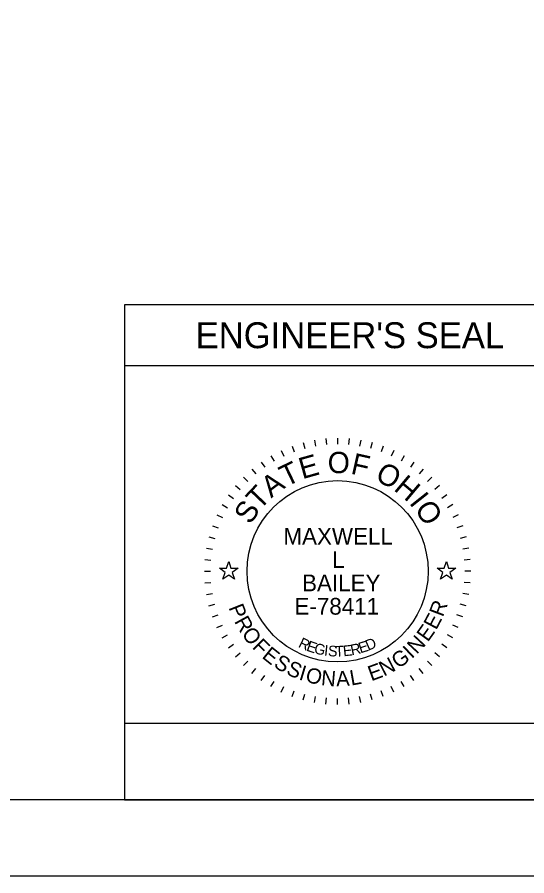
# Model space of a CAD drawing. Extents: x 0 to 34, y 0 to 22.
# Drawn here: x 6.64 to 9.99, y 0 to 5.64 of the extents above; entities that cross this region are included whole.
import ezdxf

# ---------------------------------------------------------------- set-up
doc = ezdxf.new("R2010")
doc.units = 0
for name, color, linetype in [('SH_Border', 7, 'Continuous'), ('SH_Cut_Line', 7, 'Continuous'), ('SH_Data', 7, 'Continuous'), ('SH_Seal', 7, 'Continuous')]:
    doc.layers.add(name, color=color, linetype=linetype)

msp = doc.modelspace()

# ---------------------------------------------------------------- linework, layer by layer
at = {"layer": 'SH_Border'}
msp.add_lwpolyline([(1.5, 21.5), (33.5, 21.5), (33.5, 0.5), (1.5, 0.5)], close=True, dxfattribs=at)
at = {"layer": 'SH_Cut_Line'}
msp.add_lwpolyline([(0, 0), (34, 0), (34, 22), (0, 22)], close=True, dxfattribs=at)
at = {"layer": 'SH_Data'}
for p, q in [((10.15, 3.75), (7.35, 3.75)), ((7.35, 3.75), (7.35, 0.5)), ((10.15, 3.35), (7.35, 3.35)), ((10.15, 0.5), (7.35, 0.5))]:
    msp.add_line(p, q, dxfattribs=at)
msp.add_lwpolyline([(10.15, 0.5), (10.15, 1), (7.35, 1), (7.35, 0.5)], close=True, dxfattribs=at)
at = {"layer": 'SH_Seal'}
for p, q in [((8.4507, 2.8222), (8.4644, 2.7846)), ((8.5235, 2.8452), (8.5339, 2.8065)), ((8.5981, 2.8617), (8.605, 2.8223)), ((8.6737, 2.8717), (8.6772, 2.8318)), ((8.75, 2.875), (8.75, 2.835)), ((8.8263, 2.8717), (8.8228, 2.8318)), ((8.9019, 2.8617), (8.895, 2.8223)), ((8.9765, 2.8452), (8.9661, 2.8065)), ((9.0493, 2.8222), (9.0356, 2.7846)), ((8.3802, 2.793), (8.3971, 2.7568)), ((9.1198, 2.793), (9.1029, 2.7568)), ((8.2481, 2.7168), (8.2711, 2.684)), ((8.3125, 2.7578), (8.3325, 2.7231)), ((9.1875, 2.7578), (9.1675, 2.7231)), ((9.2519, 2.7168), (9.2289, 2.684)), ((8.1876, 2.6703), (8.2133, 2.6396)), ((9.3124, 2.6703), (9.2867, 2.6396)), ((8.1313, 2.6187), (8.1596, 2.5904)), ((9.3687, 2.6187), (9.3404, 2.5904)), ((8.0797, 2.5624), (8.1104, 2.5367)), ((9.4203, 2.5624), (9.3896, 2.5367)), ((8.0332, 2.5019), (8.066, 2.4789)), ((9.4668, 2.5019), (9.434, 2.4789)), ((7.9922, 2.4375), (8.0269, 2.4175)), ((9.5078, 2.4375), (9.4731, 2.4175)), ((7.957, 2.3698), (7.9932, 2.3529)), ((9.543, 2.3698), (9.5068, 2.3529)), ((7.9278, 2.2993), (7.9654, 2.2856)), ((9.5722, 2.2993), (9.5346, 2.2856)), ((7.9048, 2.2265), (7.9435, 2.2161)), ((9.5952, 2.2265), (9.5565, 2.2161)), ((7.8883, 2.1519), (7.9277, 2.145)), ((9.6117, 2.1519), (9.5723, 2.145)), ((7.8783, 2.0763), (7.9182, 2.0728)), ((9.6217, 2.0763), (9.5818, 2.0728)), ((7.875, 2), (7.915, 2)), ((9.625, 2), (9.585, 2)), ((7.8783, 1.9237), (7.9182, 1.9272)), ((9.6217, 1.9237), (9.5818, 1.9272)), ((7.8883, 1.8481), (7.9277, 1.855)), ((9.6117, 1.8481), (9.5723, 1.855)), ((7.9048, 1.7735), (7.9435, 1.7839)), ((9.5952, 1.7735), (9.5565, 1.7839)), ((7.9278, 1.7007), (7.9654, 1.7144)), ((9.5722, 1.7007), (9.5346, 1.7144)), ((7.957, 1.6302), (7.9932, 1.6471)), ((9.543, 1.6302), (9.5068, 1.6471)), ((7.9922, 1.5625), (8.0269, 1.5825)), ((9.5078, 1.5625), (9.4731, 1.5825)), ((8.0332, 1.4981), (8.066, 1.5211)), ((9.4668, 1.4981), (9.434, 1.5211)), ((8.0797, 1.4376), (8.1104, 1.4633)), ((9.4203, 1.4376), (9.3896, 1.4633)), ((8.1313, 1.3813), (8.1596, 1.4096)), ((8.1876, 1.3297), (8.2133, 1.3604)), ((9.3124, 1.3297), (9.2867, 1.3604)), ((9.3687, 1.3813), (9.3404, 1.4096)), ((8.2481, 1.2832), (8.2711, 1.316)), ((9.2519, 1.2832), (9.2289, 1.316)), ((8.3125, 1.2422), (8.3325, 1.2769)), ((8.3802, 1.207), (8.3971, 1.2432)), ((9.1198, 1.207), (9.1029, 1.2432)), ((9.1875, 1.2422), (9.1675, 1.2769)), ((8.4507, 1.1778), (8.4644, 1.2154)), ((8.5235, 1.1548), (8.5339, 1.1935)), ((8.9765, 1.1548), (8.9661, 1.1935)), ((9.0493, 1.1778), (9.0356, 1.2154)), ((8.5981, 1.1383), (8.605, 1.1777)), ((8.6737, 1.1283), (8.6772, 1.1682)), ((8.75, 1.125), (8.75, 1.165)), ((8.8263, 1.1283), (8.8228, 1.1682)), ((8.9019, 1.1383), (8.895, 1.1777))]:
    msp.add_line(p, q, dxfattribs=at)
for points in [[(7.9736, 2.02), (8.0205, 2.02), (8.035, 2.0645), (8.0495, 2.02), (8.0964, 2.02), (8.0585, 1.9924), (8.073, 1.9478), (8.035, 1.9754), (7.997, 1.9478), (8.0115, 1.9924)], [(9.4036, 2.02), (9.4505, 2.02), (9.465, 2.0645), (9.4795, 2.02), (9.5264, 2.02), (9.4885, 1.9924), (9.503, 1.9478), (9.465, 1.9754), (9.427, 1.9478), (9.4415, 1.9924)]]:
    msp.add_lwpolyline(points, close=True, dxfattribs=at)
msp.add_circle((8.75, 2), 0.595, dxfattribs=at)

# ---------------------------------------------------------------- texts
at = {"layer": 'SH_Data'}
msp.add_text("ENGINEER'S SEAL", height=0.17, dxfattribs=at).set_placement((7.8176, 3.465))
at = {"layer": 'SH_Seal'}
for s, height, rotation, p in [('E', 0.14, 15.7571, (8.5184, 2.6038)), ('O', 0.14, 359.7812, (8.6847, 2.6443)), ('F', 0.14, 347.4362, (8.8311, 2.6417)), ('T', 0.14, 25.7167, (8.4116, 2.5518)), ('O', 0.14, 332.2586, (8.9898, 2.6015)), ('A', 0.14, 36.4747, (8.3134, 2.4781)), ('H', 0.14, 319.9136, (9.1132, 2.5361)), ('T', 0.14, 46.4344, (8.2383, 2.3964)), ('I', 0.14, 308.367, (9.2165, 2.4483)), ('S', 0.14, 57.1924, (8.1781, 2.3014)), ('O', 0.14, 303.1491, (9.2521, 2.4089)), ('R', 0.1, 69.2322, (9.4419, 1.6954)), ('P', 0.1, 291.494, (8.0323, 1.7621)), ('R', 0.1, 298.7311, (8.069, 1.6717)), ('E', 0.1, 61.9951, (9.3976, 1.6098)), ('E', 0.1, 54.758, (9.3433, 1.5314)), ('O', 0.1, 306.4666, (8.1155, 1.5883)), ('N', 0.1, 47.0224, (9.2702, 1.4508)), ('F', 0.1, 314.7068, (8.1843, 1.4983)), ('R', 0.07, 334.487, (8.4875, 1.5051)), ('E', 0.07, 341.04, (8.5406, 1.4801)), ('G', 0.07, 347.4752, (8.5914, 1.4618)), ('R', 0.07, 11.9184, (8.8425, 1.4474)), ('E', 0.07, 17.6836, (8.8998, 1.4602)), ('D', 0.07, 23.3052, (8.951, 1.477)), ('E', 0.1, 321.4393, (8.2478, 1.4348)), ('I', 0.07, 353.7858, (8.6591, 1.4468)), ('S', 0.07, 356.8926, (8.6858, 1.4429)), ('T', 0.07, 3.0061, (8.7357, 1.4387)), ('E', 0.07, 6.0117, (8.7889, 1.4412)), ('G', 0.1, 35.0469, (9.1481, 1.357)), ('I', 0.1, 43.287, (9.2368, 1.4214)), ('S', 0.1, 328.6764, (8.3243, 1.3752)), ('N', 0.1, 27.3113, (9.0545, 1.3075)), ('S', 0.1, 335.9134, (8.4064, 1.3266)), ('I', 0.1, 343.1505, (8.4906, 1.2897)), ('O', 0.1, 346.8859, (8.5339, 1.2751)), ('E', 0.1, 20.0742, (8.9712, 1.277)), ('N', 0.1, 355.1261, (8.6388, 1.2517)), ('A', 0.1, 2.8617, (8.7423, 1.2437)), ('L', 0.1, 10.0987, (8.8394, 1.249))]:
    msp.add_text(s, height=height, rotation=rotation, dxfattribs=at).set_placement(p)
for s, p in [('MAXWELL', (8.3941, 2.1749)), ('L', (8.7145, 2.0216)), ('BAILEY', (8.5167, 1.8684)), ('E-78411', (8.4667, 1.7151))]:
    msp.add_text(s, height=0.11, dxfattribs=at).set_placement(p)

doc.saveas('drawing.dxf')
